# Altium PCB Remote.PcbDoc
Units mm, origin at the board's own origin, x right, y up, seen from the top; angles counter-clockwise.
Board outline 74.42 x 42.55 mm, 2 copper layers (Top Layer, Bottom Layer); 44 components, 32 nets, 151 pads, 21 vias.
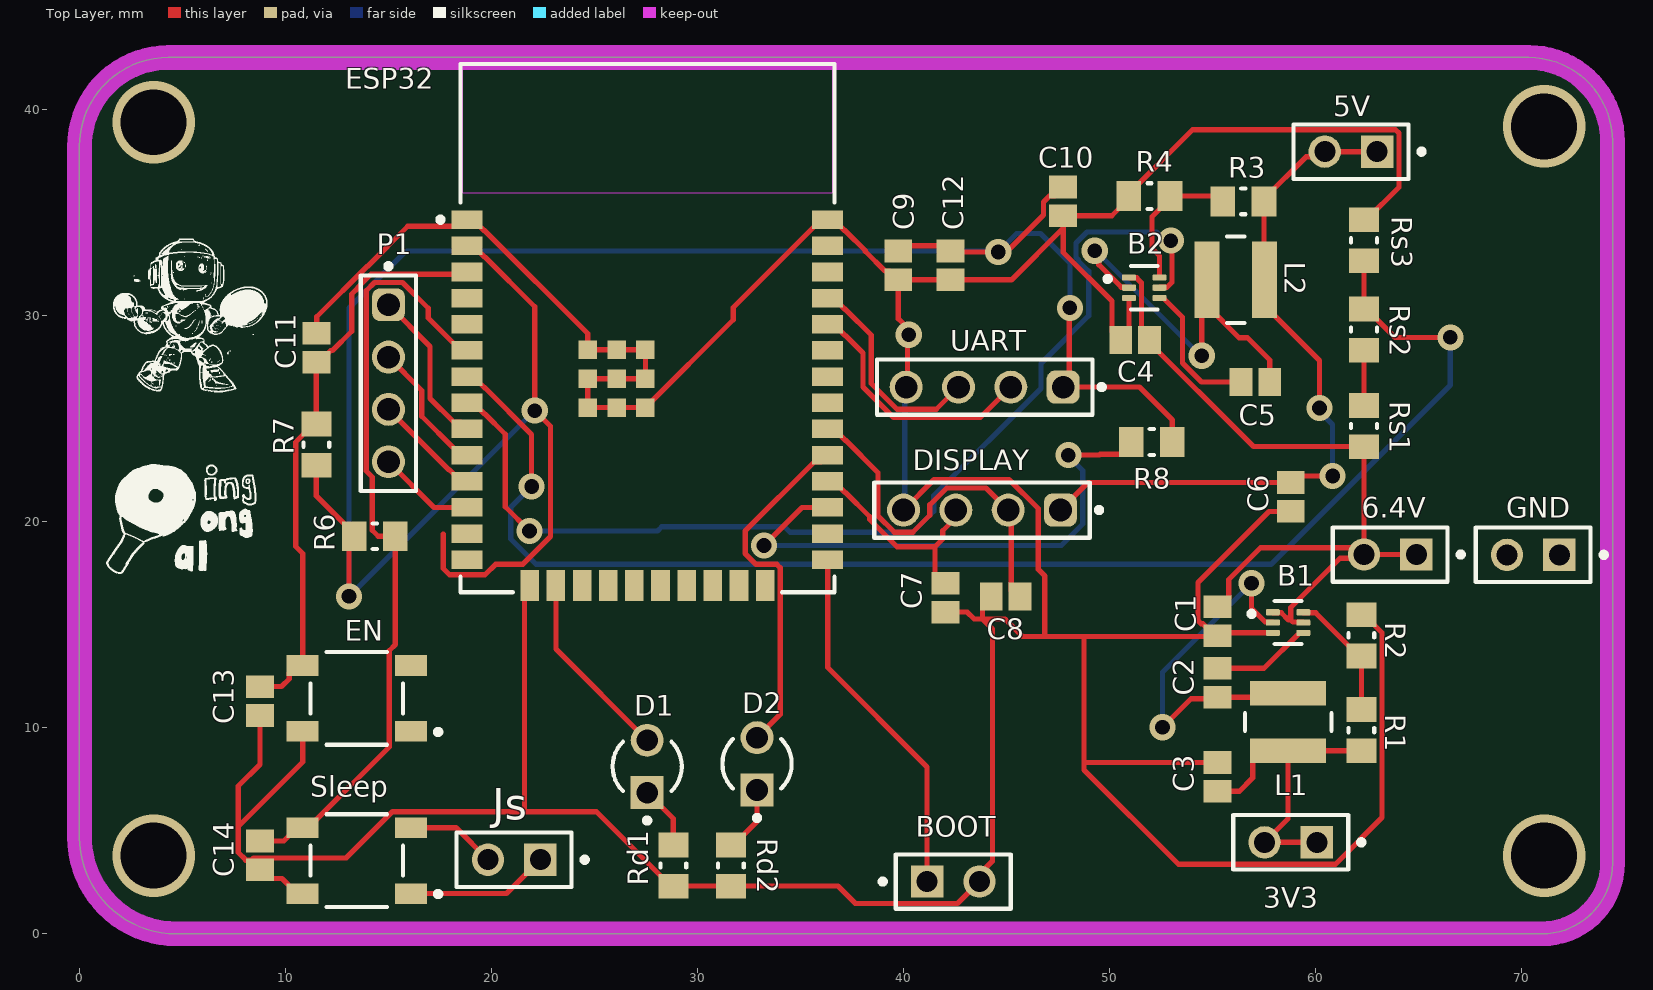
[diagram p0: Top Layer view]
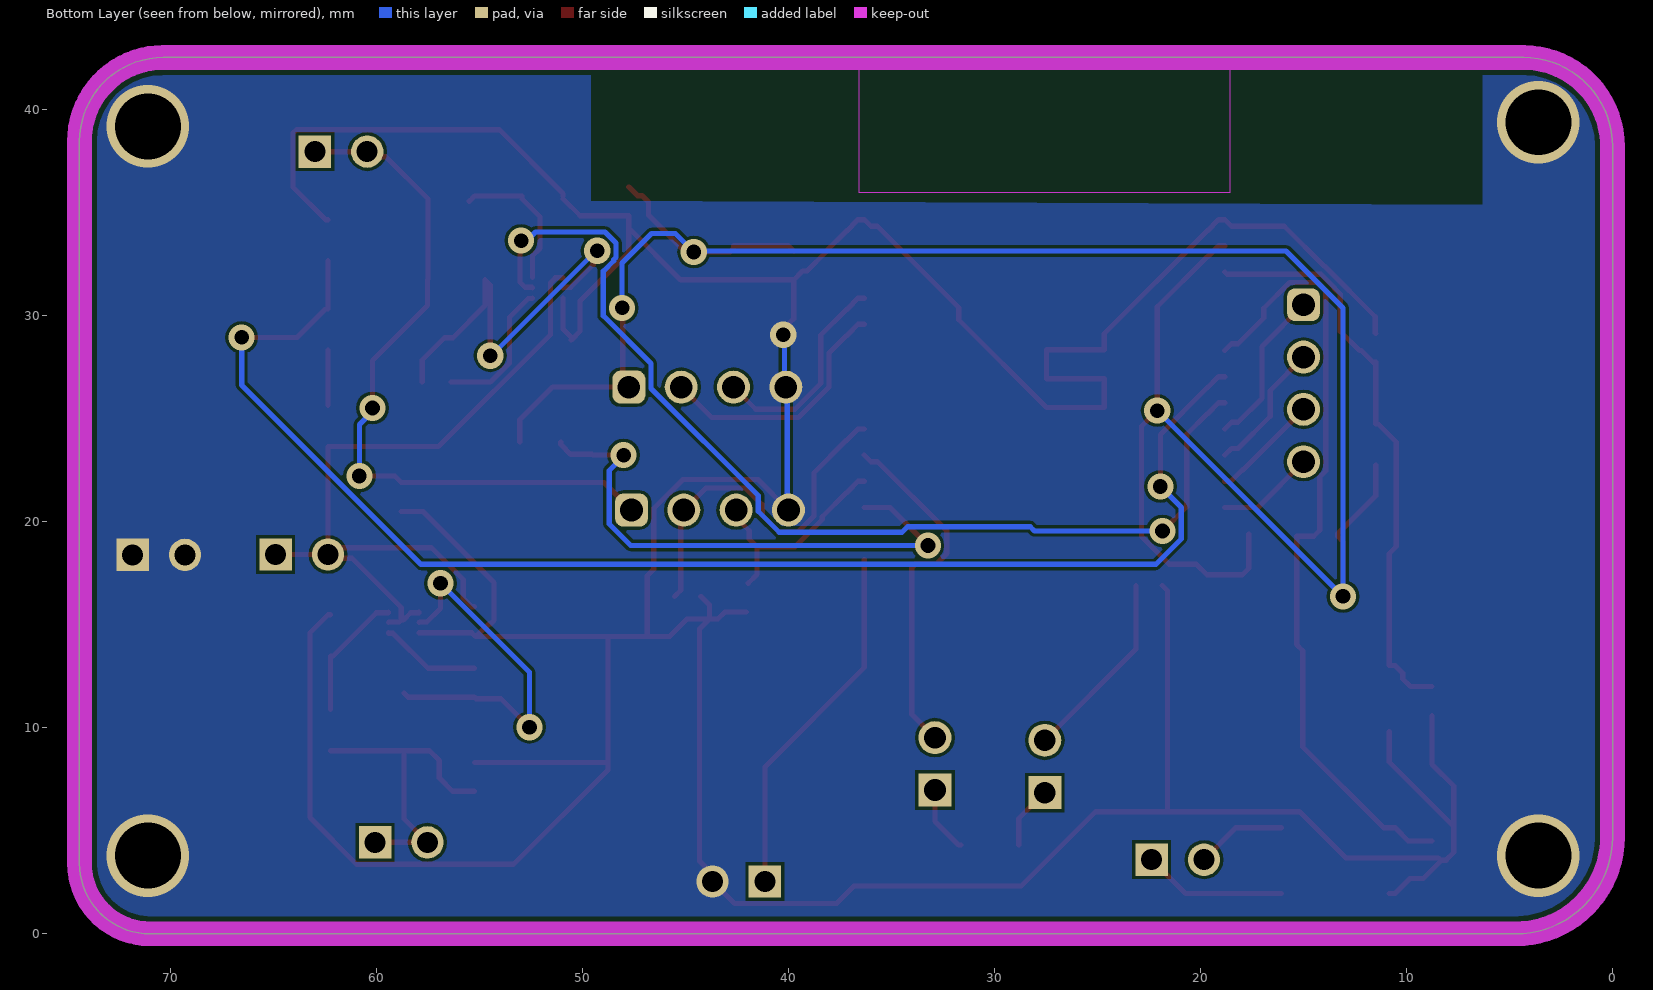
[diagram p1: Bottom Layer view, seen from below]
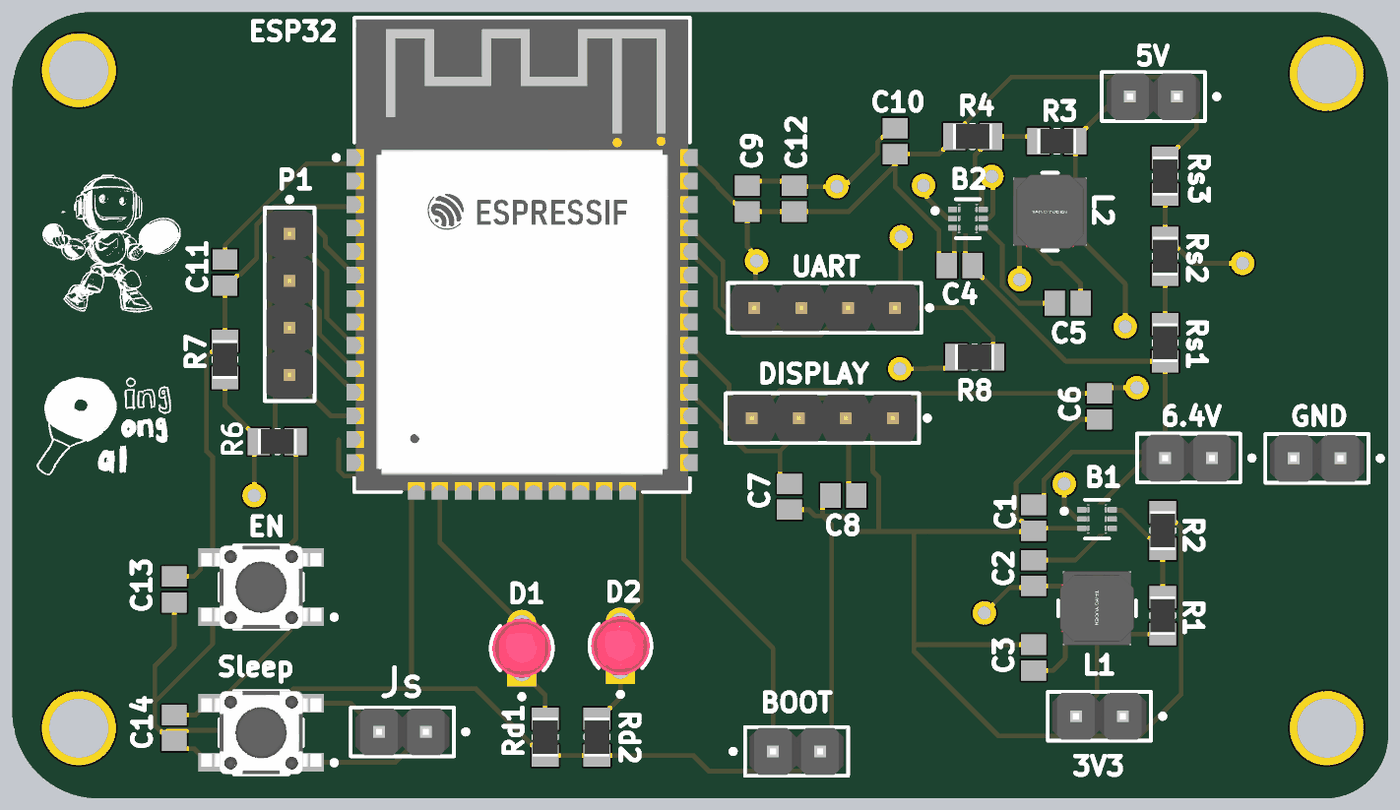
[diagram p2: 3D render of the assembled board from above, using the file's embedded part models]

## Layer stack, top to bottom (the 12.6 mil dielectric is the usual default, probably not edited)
Top Solder: solder mask 0.0102, Solder Resist, Dk 3.5
Top Layer: signal copper 0.0356
Dielectric 1: dielectric 0.32, FR-4, Dk 4.8
Bottom Layer: signal copper 0.0356
Bottom Solder: solder mask 0.0102, Solder Resist, Dk 3.5

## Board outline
0,4.699 0,38.227 cw(c4.318,38.227) 4.318,42.545 70.358,42.545 cw(c70.358,38.481) 74.422,38.481 74.422,3.429 cw(c70.993,3.429) 70.993,0 4.699,0 cw(c4.699,4.699)

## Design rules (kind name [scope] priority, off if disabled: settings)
Clearance Clearance_1 [IsPad] p1: gap=0.15 ignorepadtopadclearanceinfootprint=TRUE
Clearance Clearance_1 [OnMid vs OnMid] p2: gap=0.15 ignorepadtopadclearanceinfootprint=FALSE sourcerule=39 cellrowname=All cellrowtype=0 cellcolname=All cellcoltype=0 innerlayers=TRUE
Clearance Clearance_2 [(ExistsOnLayer('Top Layer') Or ExistsOnLayer('Bottom Layer')) vs (ExistsOnLayer('Top Layer') Or ExistsOnLayer('Bottom Layer'))] p3: gap=0.15 ignorepadtopadclearanceinfootprint=FALSE sourcerule=39 cellrowname=All cellrowtype=0 cellcolname=All cellcoltype=0 outerlayers=TRUE
Clearance [All] p4: gap=0.254 ignorepadtopadclearanceinfootprint=FALSE ismatrix=TRUE
HoleSize [All] p1: absolutevalues=TRUE maxlimit=5 minlimit=0.025 maxpercent=80.000 minpercent=20.000
MinimumSolderMaskSliver [All] p1: minsoldermaskwidth=0.09
NetAntennae NetAntenna [GND] p1 off: netantennaetolerance=100
NetAntennae [All] p2 off: netantennaetolerance=0
PlaneConnect [All] p1: planeconnectstyle=Direct reliefexpansion=0.508 reliefentries=4 reliefconductorwidth=0.254 reliefairgap=0.254
PolygonConnect [All] p1: connectstyle=Direct reliefconductorwidth=0.254 reliefentries=4 polygonreliefangle="90 Angle" airgapwidth=0.254
RoutingVias [All] p1: holewidth=0.711 width=1.27 viastyle="Through Hole" minholewidth=0.711 minwidth=1.27 maxholewidth=0.711 maxwidth=1.27
SilkToSilkClearance [All] p1: silktosilkclearance=0.16
SilkToSolderMaskClearance [IsPad] p1: minsilkscreentomaskgap=0.18 clearancetoexposedcopper=TRUE
SolderMaskExpansion [All] p1: expansion=0.102 istentingtop=FALSE
SupplyNets "Schematic Supply Nets_1" [InNet('GND')] p1: voltage=0.000
Width [All] p1: maxlimit=0.254 minlimit=0.254 preferedwidth=0.254
24 further rules are at their usual default settings.

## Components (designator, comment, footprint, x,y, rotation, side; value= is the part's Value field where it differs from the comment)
3V3 "M20-9990246" FP-M20-9990246-MFG 58.801,4.445 r180 top
5V "M20-9990246" FP-M20-9990246-MFG 61.722,37.973 r180 top
6.4V "M20-9990246" FP-M20-9990246-MFG 63.627,18.415 r180 top
B1 "TPS562231DRLR" FP-DRL0006A-MFG 58.674,15.113 r0 top
B2 "TPS562231DRLR" FP-DRL0006A-MFG 51.689,31.369 r0 top
BOOT "M20-9990246" FP-M20-9990246-MFG 42.418,2.54 r0 top
C1 "10uF" CAPC2013X88X50LL20T25 55.245,15.178 r270 top
C2 "0.1uF" CAPC2013X88X50LL20T25 55.245,12.192 r90 top
C3 "47uF" CAPC2013X88X50LL20T25 55.245,7.62 r90 top
C4 "10uF" CAPC2013X88X50LL20T25 51.243,28.829 r180 top
C5 "0.1uF" CAPC2013X88X50LL20T25 57.085,26.797 r180 top
C6 "47uF" CAPC2013X88X50LL20T25 58.801,21.209 r90 top
C7 "0.1uF" CAPC2013X88X50LL20T25 42.037,16.321 r270 top
C8 "0.1uF" CAPC2013X88X50LL20T25 44.958,16.383 r180 top
C9 "22uF" CAPC2013X88X50LL20T25 39.751,32.45 r270 top
C10 "0.1uF" CAPC2013X88X50LL20T25 47.752,35.56 r270 top
C11 "0.1uF" CAPC2013X88X50LL20T25 11.5,28.45 r270 top
C12 "10uF" CAPC2013X88X50LL20T25 42.291,32.45 r270 top
C13 "0.1uF" CAPC2013X88X50LL20T25 8.763,11.303 r270 top
C14 "0.1uF" CAPC2013X88X50LL20T25 8.763,3.81 r270 top
D1 "VSLB3940" FP-VSLB3940-MFG 27.559,8.128 r90 top
D2 "VSLB3940" FP-VSLB3940-MFG 32.893,8.255 r90 top
DISPLAY "61300411121" 61300411121 43.815,20.574 r180 top
EN "PTS647SK38SMTR2LFS" FP-PTS647SK38SMTR2LFS-MFG 13.462,11.43 r180 top
ESP32 "ESP32-WROOM-32E" FP-ESP32-WROOM-32E_M113EH-MFG 27.572,29.411 r0 top
GND "M20-9990246" FP-M20-9990246-MFG 70.57,18.4 r180 top
Js "M20-9990246" FP-M20-9990246-MFG 21.1,3.6 r180 top
L1 "3.3uH" FP-NR4012-MFG 58.674,10.287 r270 top
L2 "3.3uH" FP-NR4012-MFG 56.131,31.75 r0 top
P1 "61300411121" 61300411121 15,26.73 r270 top
R1 "45k" RESC2013X60X35ML10T20 62.23,9.89 r270 top
R2 "10k" RESC2013X60X35ML10T20 62.23,14.494 r270 top
R3 "75k" RESC2013X60X35ML10T20 56.499,35.56 r0 top
R4 "10k" RESC2013X60X35ML10T20 51.943,35.814 r0 top
R6 "10k" RESC2013X60X35ML10T20 14.335,19.304 r180 top
R7 "10k" RESC2013X60X35ML10T20 11.5,23.75 r90 top
R8 "10k" RESC2013X60X35ML10T20 52.054,23.876 r0 top
Rd1 "100" RESC2013X60X35ML10T20 28.829,3.318 r270 top
Rd2 "100" RESC2013X60X35ML10T20 31.623,3.318 r270 top
Rs1 "100k" RESC2013X60X35ML10T20 62.357,24.654 r270 top
Rs2 "100k" RESC2013X60X35ML10T20 62.357,29.337 r270 top
Rs3 "100k" RESC2013X60X35ML10T20 62.357,33.671 r270 top
Sleep "PTS647SK38SMTR2LFS" FP-PTS647SK38SMTR2LFS-MFG 13.462,3.556 r180 top
UART "61300411121" 61300411121 43.942,26.543 r180 top

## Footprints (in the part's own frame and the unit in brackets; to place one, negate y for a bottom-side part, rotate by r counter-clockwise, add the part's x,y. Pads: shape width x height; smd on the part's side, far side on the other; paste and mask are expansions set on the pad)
61300411121 [mm] "Pin Header, pitch 2.54 mm, THT, Vertical, single row, 4p"
  rrect50% 1.6x1.6 hole 1.1: 1(-3.81,0)
  round 1.6 hole 1.1: 2(-1.27,0) 3(1.27,0) 4(3.81,0)
  silkscreen extent -5.8,-1.35 5.23,1.35, body extent -5.08,-1.27 5.08,1.27, height 8.57
CAPC2013X88X50LL20T25 [mm] "Chip Capacitor, 2-Leads, Body 2.00x1.25mm, IPC High Density"
  rect 1.1x1.35 smd: 1(-0.7,0) 2(0.7,0)
  body extent -1.1,-0.72 1.1,0.72, height 0.88
FP-DRL0006A-MFG [mm]
  rrect33% 0.67x0.3 smd paste+0 mask+0: 1(-0.74,0.5) 2(-0.74,0) 3(-0.74,-0.5) 4(0.74,-0.5) 5(0.74,0) 6(0.74,0.5)
  silkscreen extent -1.9,-1.05 0.65,1.05, body extent -1.17,-1.1 1.17,1.1, height 0.25
FP-ESP32-WROOM-32E_M113EH-MFG [mm]
  rect 1.5x0.9 smd paste+0 mask+0: 1(-8.75,5.26) 2(-8.75,3.99) 3(-8.75,2.72) 4(-8.75,1.45) 5(-8.75,0.18) 6(-8.75,-1.09) 7(-8.75,-2.36) 8(-8.75,-3.63) 9(-8.75,-4.9) 10(-8.75,-6.17) 11(-8.75,-7.44) 12(-8.75,-8.71) 13(-8.75,-9.98) 14(-8.75,-11.25) 25(8.75,-11.25) 26(8.75,-9.98) 27(8.75,-8.71) 28(8.75,-7.44) 29(8.75,-6.17) 30(8.75,-4.9) 31(8.75,-3.63) 32(8.75,-2.36) 33(8.75,-1.09) 34(8.75,0.18) 35(8.75,1.45) 36(8.75,2.72) 37(8.75,3.99) 38(8.75,5.26)
  rect 0.9x1.5 smd paste+0 mask+0: 15(-5.715,-12.5) 16(-4.445,-12.5) 17(-3.175,-12.5) 18(-1.905,-12.5) 19(-0.635,-12.5) 20(0.635,-12.5) 21(1.905,-12.5) 22(3.175,-12.5) 23(4.445,-12.5) 24(5.715,-12.5)
  rect 0.9x0.9 smd paste+0 mask+0: 39(-2.9,-3.86) 39(-2.9,-2.46) 39(-2.9,-1.06) 39(-1.5,-3.86) 39(-1.5,-2.46) 39(-1.5,-1.06) 39(-0.1,-3.86) 39(-0.1,-2.46) 39(-0.1,-1.06)
  Keep-Out Layer region: -9,6.56 9,6.56 9,12.75 -9,12.75
  silkscreen extent -10.17,-12.83 9.08,12.83, body extent -9.6,-13.35 9.6,12.93, height 0.25
FP-M20-9990246-MFG [mm]
  rect 1.57x1.57 hole 1.02 paste-2539.97 mask+0: 1(-1.27,0)
  round 1.57 hole 1.02 paste-2539.97 mask+0: 2(1.27,0)
  silkscreen extent -3.55,-1.32 2.79,1.32, body extent -2.89,-1.42 2.89,1.42, height 0.25
FP-NR4012-MFG [mm]
  rect 1.2x3.7 smd paste+0 mask+0: 1(-1.4,0) 2(1.4,0)
  silkscreen extent -0.43,-2.1 0.43,2.1, body extent -2.2,-2.2 2.2,2.2, height 0.25
FP-PTS647SK38SMTR2LFS-MFG [mm]
  rect 1.55x1 smd paste+0 mask+0: 1(-2.625,1.6) 2(2.625,1.6) 3(-2.625,-1.6) 4(2.625,-1.6)
  silkscreen extent -4.08,-2.25 2.25,2.25, body extent -3.5,-2.35 3.5,2.35, height 0.25
FP-VSLB3940-MFG [mm]
  rect 1.6x1.6 hole 1.05 paste-2539.97 mask+0: 1(-1.27,0)
  round 1.6 hole 1.05 paste-2539.97 mask+0: 2(1.27,0)
  silkscreen extent -2.75,-1.68 1.2,1.68, body extent -2.32,-2.32 2.32,2.32, height 0.25
RESC2013X60X35ML10T20 [mm] "Chip Resistor, 2-Leads, Body 2.1x1.35mm, IPC Low Density"
  rect 1.2x1.45 smd: 1(-1,0) 2(1,0)
  silkscreen extent -0.1,-0.63 0.1,0.63, body extent -1.05,-0.68 1.05,0.67, height 0.6

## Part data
3V3 5V 6.4V BOOT GND Js: library part CMP-15831-000009-1, "CONN HEADER VERT 2POS 2.54MM", Current Rating=3A, Manufacturer=Harwin, Temperature="-40°C to +105°C", Temperature Range High=+105°C, Temperature Range Low=-40°C
B1 B2: library part CMP-04918-000372-1, "POWER MANAGEMENT"
C1 C2 C3 C4 C5 C6 C7 C8 C9 C10 C11 C12 C13 C14: library part CMP-2007-00266-1, Manufacturer=Kemet, Part Number=C0805C103K5RACTU
D1 D2: library part CMP-00030-18785862-1, "VSLB3940 940 nm 100 mA ±22° Through Hole High Speed Infrared Emitting Diode - T-1", Case/Package=T, Forward Current=100mA, Forward Voltage=1.35V, Max Operating Temperature=85°C, Max Power Dissipation=160mW, Min Operating Temperature=-25°C, Reverse Voltage=5V
DISPLAY P1 UART: library part CMP-1502-01064-3, Color=Black, Contact Resistance=20mΩ, Current Rating=3A, Max Operating Temperature=105°C, Min Operating Temperature=-40°C, Operating Supply Voltage=250V
EN Sleep: library part CMP-10040-000033-1, "TACT 4.5 X 4.5, 3.8 MM H, 2.5N,", Max Operating Temperature=70°C, Min Operating Temperature=-20°C, Operating Force=250gf, Ratings=IP40
ESP32: library part CMP-194065-000012-1, "RX TXRX MOD WIFI TRACE ANT SMD"
L1 L2: library part CMP-14484-001001-1, "SMD Power Inductors 3.3uH ±20% 1.4A 84mΩ", Case/Package=4012, Current Rating=1.7A, DC Resistance (DCR)=84mR, Inductance Tolerance=20%, Max Operating Temperature=125°C, Min Operating Temperature=-25°C, Package Quantity=1, Resistor Type=Wirewound, Saturation Current=1.4A, Self Resonant Frequency=60MHz, Test Frequency=100kHz
R1 R2 R3 R4 R6 R7 R8 Rd1 Rd2 Rs1 Rs2 Rs3: library part CMP-2100-03671-1, "Chip Resistor, 1 KOhm, +/- 1%, 125 mW, -55 to 155 degC, 0805 (2012 Metric), RoHS, Tape and Reel", Case Code (Imperial)=0805, Case Code (Metric)=2012, Manufacturer=Yageo, Max Operating Temperature=155degC, Max Power Dissipation=125mW, Min Operating Temperature=-55degC, Package Description="2-Pin Surface Mounted Device, Body 2 x 1.25 mm", Package Quantity=1, Resistance=1KOhm, Temperature Coefficient=100ppm/degreesC, Tolerance=1%, Voltage Rating=150V

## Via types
v1: diameter 1.27, hole 0.711, Top Layer to Bottom Layer, 17 vias
v2: diameter 4, hole 3.2, Top Layer to Bottom Layer, 4 vias

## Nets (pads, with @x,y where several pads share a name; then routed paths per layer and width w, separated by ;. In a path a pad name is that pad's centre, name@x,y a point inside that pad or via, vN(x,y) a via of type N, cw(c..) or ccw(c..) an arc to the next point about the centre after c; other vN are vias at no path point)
5vEN: B2.5 ESP32.8 | length 52.1
  Top Layer w0.254: ESP32.8 19.122,25.781 19.665,25.238 19.687,25.238 20.668,24.257 20.668,20.734 v1(21.844,19.558) ; B2.5 52.452,31.392 52.8,31.392 53.041,31.633 53.041,33.596 v1(52.982,33.655)
  Bottom Layer w0.254: v1(21.844,19.558) 28.059,19.558 28.263,19.762 34.225,19.762 34.49,19.497 40.451,19.497 41.468,20.514 41.468,21.276 46.675,26.483 46.675,27.693 48.991,30.009 48.991,32.169 48.483,32.677 48.483,32.733 48.376,32.84 48.376,33.539 48.91,34.074 52.288,34.074 52.707,33.655 v1(52.982,33.655)
+3V3: C9.1 C10.1 C12.1 ESP32.2 R6.2 R7.1 R8.2 UART.1 | length 118
  Top Layer w0.254: R7.1 11.5,21.264 13.335,19.429 R6.2 13.081,19.05 v1(13.081,16.383) ; 17.658,19.396 17.658,17.734 17.957,17.434 19.687,17.434 20.191,17.938 21.514,17.938 22.86,19.284 22.86,24.641 22.101,25.4 v1@22.098,25.4 ; ESP32.2 19.122,33.401 19.665,32.858 19.687,32.858 22.1,30.445 v1(22.1,25.401) ; C9.1 40.005,33.404 42.67,33.404 42.67,33.269 42.839,33.1 v1(44.6,33.1) 44.794,33.294 45.194,33.294 46.8,34.9 46.8,35.525 47.112,35.837 47.329,35.837 C10.1 ; v1(48.079,30.387) 48.052,30.36 48.052,26.843 UART.1 51.457,26.543 53.054,24.946 R8.2
  Bottom Layer w0.254: v1(22.1,25.401) v1(13.081,16.383) 13.081,30.378 15.851,33.148 44.552,33.148 v1(44.6,33.1) 45.5,34 46.645,34 48.079,32.566 v1(48.079,30.387)
+5V: 5V.1 5V.2 C6.2 DISPLAY.1 L2.2 R3.2 | length 35.2
  Top Layer w0.254: DISPLAY.1 48.96,21.909 C6.2 59.117,22.225 v1(60.833,22.225) ; v1(60.198,25.527) 60.198,27.833 57.531,30.5 L2.2 57.499,31.782 57.499,35.685 59.535,37.721 60.2,37.721 5V.2 5V.1
  Bottom Layer w0.254: v1(60.198,25.527) 60.198,25.36 60.833,24.725 v1(60.833,22.225)
+6.4V: 6.4V.1 6.4V.2 B1.1 B1.5 B2.1 C1.1 C4.1 Rs1.2 | length 39.9
  Top Layer w0.254: B2.1 50.972,31.846 51.32,31.846 51.561,31.605 51.561,29.086 56.993,23.654 Rs1.2 6.4V.2 ; C1.1 55.37,15.878 55.793,16.301 55.793,17.205 57.334,18.746 61.67,18.746 62.001,18.415 6.4V.2 ; B1.1 57.957,15.59 58.34,15.59 58.69,15.24 58.801,15.24 ; B1.5 59.391,15.136 58.905,15.136 58.801,15.24 ; 6.4V.1 6.4V.2 ; 58.801,15.24 58.801,15.848 61.191,18.238 62.18,18.238 6.4V.2
Boot: BOOT.1 ESP32.25 | length 17.6
  Top Layer w0.254: ESP32.25 36.322,12.931 41.148,8.105 BOOT.1
EN: C11.2 C13.1 EN.4 ESP32.3 R7.2 | length 28.2
  Top Layer w0.254: C13.1 9.81,12.003 10.189,12.382 10.189,12.657 10.562,13.03 EN.4 10.837,18.469 10.498,18.808 10.498,23.873 11.375,24.75 R7.2 C11.2 11.625,27.75 12.198,28.323 12.29,28.323 13.221,29.254 13.221,31.061 13.519,31.359 13.519,31.388 14.152,32.021 18.712,32.021 ESP32.3
GND: B1.3 B2.3 BOOT.2 C1.2 C3.2 C4.2 C6.1 C7.2 C8.2 C9.2 C10.2 C11.1 C12.2 C13.2 C14.2 DISPLAY.4 EN.2 ESP32.1 ESP32.15 ESP32.38 ESP32.39 GND.1 GND.2 R2.1 R4.1 Rd1.2 Rd2.2 Rs3.1 Sleep.2 UART.4 | length 264.4
  Top Layer w0.254: C14.2@8.34,3.533 9.186,2.687 9.831,2.687 10.562,1.956 Sleep.2 ; C13.2 8.763,8.227 7.707,7.171 7.707,5.218 ; EN.2 10.837,8.348 7.707,5.218 ; C11.1 11.521,29.171 11.521,29.961 13.985,32.425 14.014,32.425 15.937,34.348 18.499,34.348 ESP32.1 19.122,34.671 19.665,34.128 19.687,34.128 24.672,29.143 24.672,28.351 27.472,28.351 27.472,26.951 24.672,26.951 24.672,25.551 27.472,25.551 31.736,29.815 31.736,30.407 35.677,34.348 35.999,34.348 ESP32.38 36.622,34.671 37.165,34.128 37.187,34.128 38.149,33.166 38.149,33.135 39.111,32.173 39.328,32.173 C9.2 ; ESP32.15 21.6,16.654 21.6,5.933 ; DISPLAY.4@40.069,20.637 41.486,22.055 45.127,22.055 46.548,20.634 46.548,17.693 46.863,17.378 46.863,14.436 ; UART.4 40.195,26.607 40.195,29.019 v1(40.259,29.083) 40.259,29.358 39.751,29.866 C9.2 ; C7.2 43.093,15.621 43.434,15.28 43.835,15.28 ; C8.2 43.835,15.96 43.835,15.28 ; C10.2 47.752,34.252 ; C10.2@47.877,34.86 50.114,34.86 R4.1@50.943,35.689 ; C4.2 50.12,29.252 50.12,30.723 47.752,33.091 47.752,34.252 ; C4.2@50.543,28.954 50.949,29.36 B2.3 ; R4.1 50.943,35.939 54.039,39.035 63.892,39.035 64.054,38.873 64.054,36.243 62.482,34.671 Rs3.1 ; C3.2 48.768,8.32 ; B1.3 55.38,14.613 C1.2 ; C6.1 57.745,20.509 54.293,17.057 54.293,15.213 54.455,15.051 54.547,15.051 55.12,14.478 C1.2 ; R2.1 62.355,15.494 63.232,14.617 63.232,5.644 60.971,3.383 53.346,3.383 48.768,7.961 48.768,8.32 ; 7.707,5.218 7.707,3.949 8.077,3.579 8.34,3.579 8.444,3.683 12.947,3.683 15.197,5.933 21.6,5.933 ; 21.6,5.933 25.089,5.933 28.704,2.318 Rd2.2 36.825,2.318 37.665,1.478 42.626,1.478 BOOT.2 43.688,2.896 44.323,3.531 44.323,14.792 43.835,15.28 ; C9.2 C12.2 45.25,31.75 47.752,34.252 ; 43.835,15.28 44.927,15.28 45.771,14.436 46.863,14.436 ; 46.863,14.436 48.768,14.436 ; 48.768,8.32 48.768,14.436 ; 48.768,14.436 55.203,14.436 C1.2
  Bottom Layer w0.254: DISPLAY.4 40.069,20.637 40.069,26.479 40.195,26.607 40.195,29.019 v1(40.259,29.083)
  other v2: 3.6,3.8 71.1,3.8 71.1,39.2 3.6,39.4
IO25: ESP32.10 P1.2 | length 6.5
  Top Layer w0.254: P1.2 16.616,26.384 16.616,25.125 18.177,23.564 18.499,23.564 ESP32.10
IO26: ESP32.11 P1.3 | length 5.3
  Top Layer w0.254: P1.3 17.946,22.514 17.979,22.514 18.522,21.971 ESP32.11
IO27: ESP32.12 P1.4 | length 4.7
  Top Layer w0.254: P1.4 17.219,20.701 ESP32.12
IO33: ESP32.9 P1.1 | length 7.8
  Top Layer w0.254: P1.1 17.02,28.52 17.02,25.991 18.177,24.834 18.499,24.834 ESP32.9
LED1: D1.2 ESP32.16 | length 9.3
  Top Layer w0.254: ESP32.16 23.127,13.83 D1.2
LED2: D2.2 ESP32.29 | length 17.3
  Top Layer w0.254: D2.2 34.014,10.646 34.014,17.776 33.852,17.938 33.023,17.938 32.85,17.938 32.316,18.472 32.316,19.557 35.677,22.918 35.999,22.918 ESP32.29
Net3V3_1: 3V3.1 3V3.2 C3.1 L1.2 R1.2 | length 15.8
  Top Layer w0.254: C3.1 56.301,6.92 56.951,7.57 56.951,8.414 57.424,8.887 L1.2 ; 3V3.1 3V3.2 58.674,5.588 L1.2 ; R1.2 62.227,8.887 L1.2
NetB1_2: B1.2 C2.1 L1.1 | length 18.1
  Top Layer w0.254: v1(52.578,10.033) 53.957,11.412 55.165,11.412 C2.1 58.479,11.492 L1.1 ; v1(56.896,17.018) 56.896,15.803 57.563,15.136 57.911,15.136 B1.2
  Bottom Layer w0.254: v1(52.578,10.033) 52.578,12.7 v1(56.896,17.018)
NetB1_4: B1.4 C2.2 | length 4.9
  Top Layer w0.254: C2.2 57.508,12.892 59.206,14.59 59.391,14.59 B1.4
NetB1_6: B1.6 R1.1 R2.2 | length 6.3
  Top Layer w0.254: B1.6 59.437,15.59 60.009,15.59 62.105,13.494 R2.2 R1.1
NetB2_2: B2.2 C5.1 L2.1 | length 20.2
  Top Layer w0.254: v1(49.288,33.162) 49.483,32.967 49.483,32.488 50.578,31.392 50.926,31.392 B2.2 ; v1(54.483,28.067) 54.483,31.502 L2.1 54.731,30.5 56.291,28.94 56.698,28.94 57.785,27.853 C5.1
  Bottom Layer w0.254: v1(49.288,33.162) 49.338,33.162 54.433,28.067 v1(54.483,28.067)
NetB2_4: B2.4 C5.2 | length 6.9
  Top Layer w0.254: B2.4 52.452,30.846 52.637,30.846 53.55,29.933 53.55,27.71 54.463,26.797 C5.2
NetB2_6: B2.6 R3.1 R4.2 | length 7.1
  Top Layer w0.254: B2.6 52.429,32.918 52.07,33.277 52.07,34.816 52.943,35.689 R4.2 55.245,35.814 R3.1
NetD1_1: D1.1 Rd1.1 | length 3.1
  Top Layer w0.254: D1.1 28.829,5.588 Rd1.1
NetD2_1: D2.1 Rd2.1 | length 3.3
  Top Layer w0.254: Rd2.1 31.748,4.318 32.893,5.463 D2.1
NetESP32_27: ESP32.27 R8.1 | length 26.6
  Top Layer w0.254: v1(33.228,18.85) 35.079,20.701 ESP32.27 ; v1(48.006,23.241) 49.51,23.241 49.547,23.278 50.581,23.278 51.054,23.751 R8.1
  Bottom Layer w0.254: v1(33.228,18.85) 47.658,18.85 48.702,19.894 48.702,22.5 48.133,23.069 v1@48.133,23.114
NetJs_1: Js.1 Sleep.1 | length 7
  Top Layer w0.254: Sleep.1 20.726,1.956 21.9,3.13 21.9,3.2 21.97,3.2 Js.1
NetJs_2: Js.2 Sleep.3 | length 4.4
  Top Layer w0.254: Sleep.3 18.274,5.156 Js.2
NetRs1_1: Rs1.1 Rs2.2 | length 2.7
  Top Layer w0.254: Rs1.1 Rs2.2
RxD: C8.1 DISPLAY.2 ESP32.30 | length 18.1
  Top Layer w0.254: ESP32.30 36.622,24.511 37.165,23.968 37.187,23.968 38.768,22.387 38.768,20.288 39.559,19.497 40.451,19.497 41.275,20.321 41.275,20.827 42.099,21.651 44.008,21.651 45.235,20.424 45.235,16.679 C8.1@45.531,16.383
RXD0: ESP32.34 UART.2 | length 12.3
  Top Layer w0.254: ESP32.34 36.622,29.591 37.165,29.048 37.187,29.048 38.032,28.202 38.032,26.548 39.519,25.062 43.731,25.062 UART.2
Sleep: C14.1 ESP32.6 R6.1 Sleep.4 | length 38.2
  Top Layer w0.254: C14.1 9.916,4.51 10.562,5.156 11.112,5.156 15.035,9.079 15.035,13.743 15.335,14.043 R6.1 14.503,19.304 14.212,19.595 14.212,22.185 13.923,22.474 13.923,31.22 14.32,31.617 15.68,31.617 16.929,30.369 16.929,29.892 18.177,28.644 18.499,28.644 ESP32.6
TxD: C7.1 DISPLAY.3 ESP32.28 | length 10.8
  Top Layer w0.254: ESP32.28 36.622,21.971 37.165,21.428 37.187,21.428 38.364,20.251 38.364,20.12 39.689,18.796 41.529,18.796 ; C7.1@41.955,17.018 41.529,17.444 41.529,18.796 ; DISPLAY.3 42.545,20.21 41.908,19.573 41.908,19.175 41.529,18.796
TXD0: ESP32.35 UART.3 | length 10.4
  Top Layer w0.254: ESP32.35 36.622,30.861 37.165,30.318 37.187,30.318 38.436,29.068 38.436,26.716 39.686,25.466 41.595,25.466 UART.3
Vsense: ESP32.7 Rs2.1 Rs3.2 | length 68.9
  Top Layer w0.254: ESP32.7 19.122,27.051 19.665,26.508 19.687,26.508 21.948,24.247 v1(21.948,21.717) ; Rs3.2 Rs2.1 62.482,30.337 63.863,28.956 v1(66.548,28.956)
  Bottom Layer w0.254: v1(21.948,21.717) 20.932,20.701 20.932,19.18 22.174,17.938 57.836,17.938 66.548,26.65 v1(66.548,28.956)
pads on no net: EN.1 EN.3 ESP32.4 ESP32.5 ESP32.13 ESP32.14 ESP32.17 ESP32.18 ESP32.19 ESP32.20 ESP32.21 ESP32.22 ESP32.23 ESP32.24 ESP32.26 ESP32.31 ESP32.32 ESP32.33 ESP32.36 ESP32.37

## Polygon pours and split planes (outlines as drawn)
GND on Bottom Layer "Bottom Layer-GND" (solid, pour order 2): 0,38.227 0,4.699 ccw(c4.699,4.699) 4.699,0 70.993,0 ccw(c70.993,3.429) 74.422,3.429 74.422,38.481 ccw(c70.358,38.481) 70.358,42.545 49.655,42.545 49.7,42.5 49.6,42.4 49.6,35.6 6.3,35.4 6.3,42.545 4.318,42.545 ccw(c4.318,38.227)

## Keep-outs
Keep-Out Layer:
  the board outline again, w1.2

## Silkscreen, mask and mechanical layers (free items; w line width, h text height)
Top Overlay:
  drawing of 288 lines, arcs and shapes, not listed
